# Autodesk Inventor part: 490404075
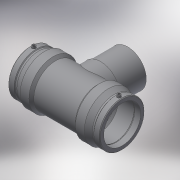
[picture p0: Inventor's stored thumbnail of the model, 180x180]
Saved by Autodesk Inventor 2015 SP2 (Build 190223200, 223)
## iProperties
Created: 2017-06
Part Number: 490404075
Material: Generic
Description: PLASSON TEE 75-75-75
Document SubType Name: Modeling
Designer: KIM
Mass: 618.888 g
Surface Area: 1436.62 cm^2
Volume: 618.888 cm^3
Density: 1 g/cm^3
Appearance: Default
Author: KIM
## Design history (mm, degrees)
derived "490404.ipt"
feature "Solid1::490404.ipt"
tag "TaggingFeature1"
body "Solid1"
other parameters: "d0" = 196, "d1" = 75, "d2" = 96, "d3" = 63, "d4" = 49, "d5" = 86.4, "d6" = 71.25, "d7" = 75, "d8" = 168 deg, "d10" = 25.2, "d11" = 8.4, "d13" = 196, "d14" = 17.6296, "d17" = 67.5, "d18" = 75, "d19" = 3.52592, "d20" = 168 deg, "d22" = 89.28, "d23" = 96, "d24" = 86.6016, "d25" = 135 deg, "d26" = 137.2, "d27" = 135 deg, "d29" = 62, "d30" = 15, "d31" = 78.4, "d34" = 5 deg, "d35" = 15, "d39" = 5 deg, "d40" = 9.6, "d41" = 4.8, "d42" = 6, "d43" = 0, "d45" = 4, "d46" = 14, "d47" = 0, "d48" = -129, "d49" = 75, "d51" = 0, "d54" = 0, "d55" = 86.4, "d56" = 96, "d57" = 68.6, "d58" = 135 deg, "d59" = 63, "d60" = 63, "d61" = 135 deg, "d62" = 129, "d72" = 89.18, "d73" = 44.59, "d74" = -129, "d75" = 78.75, "d77" = 0, "d80" = 0, "d81" = 75, "d82" = 81, "d83" = 0, "d84" = 3, "d85" = 0, "d86" = 3, "d87" = 0, "d88" = 18.27, "d89" = 4.5675, "d90" = 18.27, "d_" = 75, "L_" = 196, "L_1" = 63, "D_" = 96, "A_" = 62, "d_2" = 12, "H_" = 129
